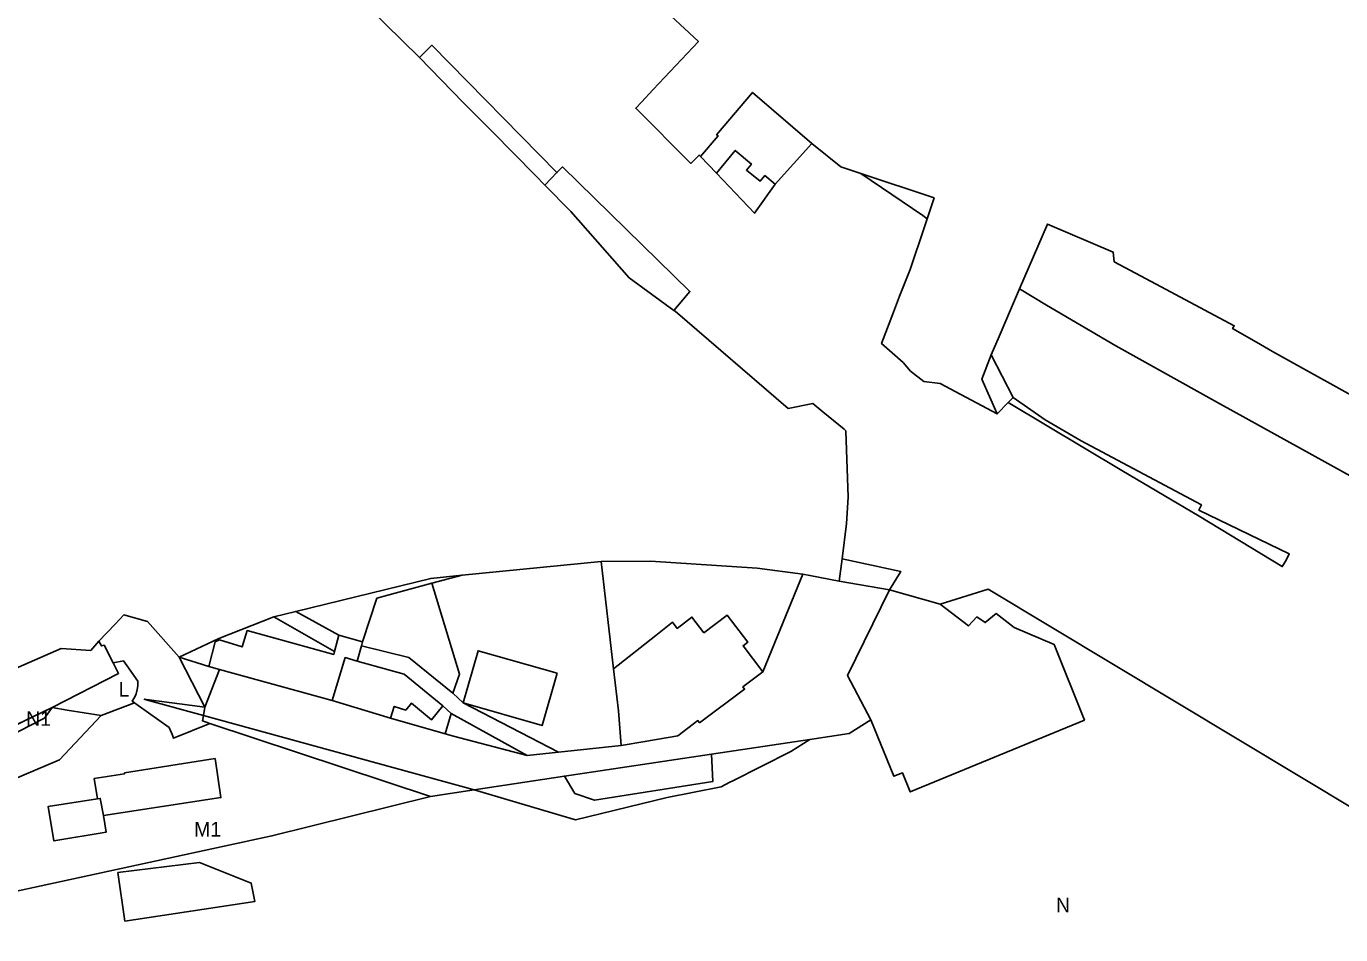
# Model space of a CAD drawing. Extents: x -749314 to -746497, y -1026537 to -1024935.
# Drawn here: x -748467.6 to -748241.9, y -1025301.1 to -1025145.2 of the extents above; entities that cross this region are included whole.
import ezdxf

# ---------------------------------------------------------------- set-up
doc = ezdxf.new("R2010")
doc.units = 0
for name, color, linetype in [('Default', 7, 'Continuous'), ('K_CD1', 7, 'Continuous'), ('K_DOSZDC1', 7, 'Continuous'), ('K_DOSZDC2', 7, 'Continuous'), ('K_JVL', 7, 'Continuous'), ('K_NH_SZDC', 7, 'Continuous'), ('K_SZDC1', 7, 'Continuous')]:
    doc.layers.add(name, color=color, linetype=linetype)

msp = doc.modelspace()

# ---------------------------------------------------------------- linework, layer by layer
at = {"layer": 'Default'}
msp.add_lwpolyline([(-748481.42, -1025296.24), (-748425.39, -1025284.16), (-748398.16, -1025277.36), (-748390.67, -1025276.23), (-748373.29, -1025281.41), (-748357.56, -1025277.57), (-748348.28, -1025275.71), (-748346.76, -1025274.95), (-748346.26, -1025274.69), (-748336.31, -1025269.68), (-748333.02, -1025267.6), (-748326.29, -1025266.59), (-748322.55, -1025264.22), (-748318.62, -1025273.91), (-748317.14, -1025273.32), (-748315.81, -1025276.61), (-748285.9, -1025264.26), (-748291.07, -1025251.31), (-748297.93, -1025248.38), (-748301.07, -1025245.99), (-748302.96, -1025247.53), (-748304.39, -1025246.58), (-748305.81, -1025248.11), (-748310.66, -1025244.41), (-748302.42, -1025241.8), (-748259.36, -1025267.68), (-748156.97, -1025329.23)], dxfattribs=at)
for points in [[(-748507.76, -1025270.01), (-748500.87, -1025267.55), (-748481.26, -1025260.55), (-748461.55, -1025251.98), (-748456.49, -1025252.31), (-748455.09, -1025250.76), (-748454.67, -1025251.54), (-748454.2, -1025251.4), (-748452.63, -1025254.43), (-748451.72, -1025256.27), (-748463.12, -1025262.12), (-748476.84, -1025268.7), (-748490.67, -1025269.69)], [(-748373.41, -1025276.86), (-748375.18, -1025273.89), (-748390.67, -1025276.23), (-748373.29, -1025281.41), (-748357.56, -1025277.57), (-748348.28, -1025275.71), (-748346.76, -1025274.95), (-748346.26, -1025274.69), (-748336.31, -1025269.68), (-748333.02, -1025267.6), (-748349.91, -1025270.15), (-748349.68, -1025274.79), (-748369.98, -1025278.03)], [(-748349.91, -1025270.15), (-748375.18, -1025273.89), (-748373.41, -1025276.86), (-748369.98, -1025278.03), (-748349.68, -1025274.79)], [(-748428.95, -1025292.23), (-748437.85, -1025288.69), (-748451.83, -1025290.44), (-748450.64, -1025298.75), (-748428.35, -1025295.41)], [(-748451.83, -1025290.44), (-748450.64, -1025298.75), (-748428.35, -1025295.41), (-748428.95, -1025292.23), (-748437.85, -1025288.69)]]:
    msp.add_lwpolyline(points, close=True, dxfattribs=at)
at = {"layer": 'K_CD1'}
for points in [[(-748397.91, -1025240.78), (-748392.75, -1025239.43), (-748368.84, -1025237.04), (-748366.72, -1025255.47), (-748365.9, -1025262.69), (-748365.42, -1025268.61), (-748376.21, -1025269.79), (-748392.57, -1025261.31), (-748394.34, -1025259.67), (-748393.18, -1025256.4)], [(-748413.88, -1025249.73), (-748409.82, -1025250.87), (-748407.37, -1025243.38), (-748397.91, -1025240.78), (-748392.75, -1025239.43), (-748398.11, -1025239.97), (-748421.29, -1025245.63)], [(-748409.82, -1025250.87), (-748410.01, -1025251.52), (-748401.89, -1025253.55), (-748394.34, -1025259.67), (-748393.18, -1025256.4), (-748397.91, -1025240.78), (-748407.37, -1025243.38)], [(-748343.7, -1025250.93), (-748347.24, -1025246.25), (-748351.22, -1025249.28), (-748353.27, -1025246.6), (-748355.8, -1025248.53), (-748356.59, -1025247.5), (-748359.49, -1025249.78), (-748366.72, -1025255.47), (-748365.9, -1025262.69), (-748365.42, -1025268.61), (-748361.35, -1025267.97), (-748355.72, -1025266.95), (-748352.26, -1025264.36), (-748351.98, -1025264.74), (-748344.24, -1025258.97), (-748344.54, -1025258.57), (-748341.12, -1025256), (-748344.5, -1025251.53)], [(-748376.44, -1025256.25), (-748389.99, -1025252.38), (-748392.57, -1025261.31), (-748379.01, -1025265.21)], [(-748452.63, -1025254.43), (-748450.89, -1025254.09), (-748450.31, -1025254.91), (-748448.41, -1025257.6), (-748448.41, -1025258.33), (-748448.5, -1025259.06), (-748448.7, -1025259.76), (-748448.98, -1025260.42), (-748449.36, -1025261.05), (-748448.96, -1025261.34), (-748454.73, -1025263.51), (-748460.54, -1025262.55), (-748463.12, -1025262.12), (-748451.72, -1025256.27)], [(-748402.41, -1025262.56), (-748404.38, -1025261.94), (-748405.01, -1025263.94), (-748395.64, -1025266.64), (-748394.62, -1025263.16), (-748396.07, -1025261.8), (-748398.01, -1025264.24), (-748401.44, -1025261.39)], [(-748476.84, -1025268.7), (-748473.31, -1025268.45), (-748473.2, -1025268.39), (-748464.42, -1025263.92), (-748463.12, -1025262.12), (-748460.54, -1025262.55), (-748454.73, -1025263.51), (-748461.87, -1025271.11), (-748472.17, -1025275.42), (-748531.33, -1025278.43), (-748493.03, -1025276.48)], [(-748463.12, -1025262.12), (-748464.42, -1025263.92), (-748473.2, -1025268.39), (-748473.31, -1025268.45), (-748490.67, -1025269.69), (-748476.84, -1025268.7)], [(-748436.05, -1025264.85), (-748398.16, -1025277.36), (-748390.67, -1025276.23), (-748437.15, -1025263.49), (-748437.32, -1025264.43)], [(-748395.64, -1025266.64), (-748394.19, -1025267.02), (-748381.58, -1025270.37), (-748394.62, -1025263.16)], [(-748455.36, -1025277.8), (-748463.83, -1025279.13), (-748462.81, -1025285), (-748453.87, -1025283.51), (-748454.31, -1025280.65), (-748434.14, -1025277.57), (-748435.16, -1025270.88), (-748450.7, -1025273.33), (-748450.68, -1025273.48), (-748455.91, -1025274.3)], [(-748434.14, -1025277.57), (-748435.16, -1025270.88), (-748450.7, -1025273.33), (-748450.68, -1025273.48), (-748455.91, -1025274.3), (-748455.36, -1025277.8), (-748454.86, -1025277.72), (-748454.31, -1025280.65)], [(-748454.86, -1025277.72), (-748455.36, -1025277.8), (-748463.83, -1025279.13), (-748462.81, -1025285), (-748453.87, -1025283.51), (-748454.31, -1025280.65)]]:
    msp.add_lwpolyline(points, close=True, dxfattribs=at)
msp.add_lwpolyline([(-748472.17, -1025275.42), (-748461.87, -1025271.11), (-748454.73, -1025263.51), (-748448.96, -1025261.34), (-748448.37, -1025261.75), (-748443.02, -1025265.56), (-748442.47, -1025266.89), (-748442.27, -1025267.38), (-748436.05, -1025264.85), (-748398.16, -1025277.36), (-748425.39, -1025284.16), (-748481.42, -1025296.24)], dxfattribs=at)
at = {"layer": 'K_DOSZDC1'}
for points in [[(-748361.64, -1025138.97), (-748352.17, -1025147.81), (-748359.92, -1025156.05), (-748361.94, -1025158.22), (-748362.94, -1025159.29), (-748353.45, -1025168.75), (-748352.05, -1025167.33), (-748351.8, -1025167.57), (-748349.06, -1025170.45), (-748342.56, -1025177.29), (-748338.97, -1025172.34), (-748332.71, -1025165.34), (-748327.72, -1025169.36), (-748324.28, -1025170.5), (-748313.64, -1025177.68), (-748312.91, -1025178.26), (-748313.36, -1025179.62), (-748315.81, -1025186.96), (-748317.62, -1025191.55), (-748318.68, -1025194.3), (-748320.73, -1025199.67), (-748318.92, -1025201.26), (-748317.03, -1025202.92), (-748315.73, -1025204.43), (-748313.48, -1025206.18), (-748310.68, -1025206.52), (-748300.87, -1025211.73), (-748298.96, -1025209.79), (-748279.45, -1025221.42), (-748266.2, -1025229.26), (-748251.92, -1025237.92), (-748251.29, -1025236.96), (-748250.72, -1025235.77), (-748266.23, -1025228.28), (-748265.8, -1025227.35), (-748286.48, -1025216.34), (-748292.62, -1025212.73), (-748298.12, -1025208.94), (-748301.88, -1025201.58), (-748300.52, -1025198.43), (-748298.39, -1025193.46), (-748297.03, -1025190.29), (-748292.38, -1025193.05), (-748280.52, -1025200.07), (-748262.56, -1025210.09), (-748239.75, -1025222.62)], [(-748156.97, -1025329.23), (-748259.36, -1025267.68), (-748302.42, -1025241.8), (-748310.66, -1025244.41), (-748319.38, -1025241.93), (-748317.42, -1025238.76), (-748327.51, -1025236.61), (-748326.73, -1025230.56), (-748326.47, -1025226.05), (-748326.87, -1025214.62), (-748327.16, -1025214.38), (-748330.78, -1025211.39), (-748332.52, -1025209.93), (-748336.74, -1025210.78), (-748356.18, -1025194.13), (-748356.37, -1025193.99), (-748355.74, -1025193.24), (-748353.64, -1025190.72), (-748375.48, -1025169.34), (-748376.46, -1025170.34), (-748397.91, -1025148.49), (-748400.03, -1025150.58), (-748408.87, -1025141.96)]]:
    msp.add_lwpolyline(points, dxfattribs=at)
at = {"layer": 'K_DOSZDC2'}
for points in [[(-748298.12, -1025208.94), (-748301.88, -1025201.58), (-748303.52, -1025205.77), (-748300.87, -1025211.73), (-748298.96, -1025209.79)], [(-748298.12, -1025208.94), (-748298.96, -1025209.79), (-748279.45, -1025221.42), (-748266.2, -1025229.26), (-748251.92, -1025237.92), (-748251.29, -1025236.96), (-748250.72, -1025235.77), (-748266.23, -1025228.28), (-748265.8, -1025227.35), (-748286.48, -1025216.34), (-748292.62, -1025212.73)], [(-748319.38, -1025241.93), (-748317.42, -1025238.76), (-748327.51, -1025236.61), (-748328, -1025240.41)]]:
    msp.add_lwpolyline(points, close=True, dxfattribs=at)
at = {"layer": 'K_JVL'}
for points in [[(-748378.54, -1025172.46), (-748376.46, -1025170.34), (-748397.91, -1025148.49), (-748400.03, -1025150.58), (-748392.55, -1025158.28), (-748389.34, -1025161.49), (-748387.51, -1025163.33), (-748380.2, -1025170.79)], [(-748356.37, -1025193.99), (-748355.74, -1025193.24), (-748353.64, -1025190.72), (-748375.48, -1025169.34), (-748376.46, -1025170.34), (-748378.54, -1025172.46), (-748374.05, -1025176.99), (-748364.05, -1025188.38)], [(-748324.28, -1025170.5), (-748313.64, -1025177.68), (-748312.91, -1025178.26), (-748311.72, -1025174.67)], [(-748231.61, -1025227.23), (-748231.28, -1025225.26), (-748226.09, -1025216.29), (-748236.47, -1025210.53), (-748253.59, -1025201.03), (-748256.36, -1025199.44), (-748260.46, -1025197.09), (-748260.18, -1025196.6), (-748275.28, -1025188.56), (-748280.8, -1025185.62), (-748280.97, -1025183.96), (-748292.24, -1025179.16), (-748297.03, -1025190.29), (-748292.38, -1025193.05), (-748280.52, -1025200.07), (-748262.56, -1025210.09), (-748239.75, -1025222.62)], [(-748342.1, -1025238.22), (-748360.41, -1025236.99), (-748368.84, -1025237.04), (-748366.72, -1025255.47), (-748359.49, -1025249.78), (-748356.59, -1025247.5), (-748355.8, -1025248.53), (-748353.27, -1025246.6), (-748351.22, -1025249.28), (-748347.24, -1025246.25), (-748343.7, -1025250.93), (-748344.5, -1025251.53), (-748341.12, -1025256), (-748334.22, -1025239.24)], [(-748375.18, -1025273.89), (-748349.91, -1025270.15), (-748333.02, -1025267.6), (-748326.29, -1025266.59), (-748322.55, -1025264.22), (-748326.56, -1025256.6), (-748319.38, -1025241.93), (-748328, -1025240.41), (-748333.03, -1025239.44), (-748334.22, -1025239.24), (-748341.12, -1025256), (-748344.54, -1025258.57), (-748344.24, -1025258.97), (-748351.98, -1025264.74), (-748352.26, -1025264.36), (-748355.72, -1025266.95), (-748361.35, -1025267.97), (-748365.42, -1025268.61), (-748376.21, -1025269.79), (-748381.58, -1025270.37), (-748394.19, -1025267.02), (-748395.64, -1025266.64), (-748405.01, -1025263.94), (-748415.04, -1025260.93), (-748434.4, -1025255.6), (-748436.89, -1025262.07), (-748437.15, -1025263.49), (-748390.67, -1025276.23)], [(-748414.64, -1025252.51), (-748413.88, -1025249.73), (-748421.29, -1025245.63), (-748425.08, -1025246.56)], [(-748446.77, -1025247.37), (-748450.79, -1025246.22), (-748452.32, -1025247.83), (-748455.09, -1025250.76), (-748454.67, -1025251.54), (-748454.2, -1025251.4), (-748452.63, -1025254.43), (-748450.89, -1025254.09), (-748450.31, -1025254.91), (-748448.41, -1025257.6), (-748448.41, -1025258.33), (-748448.5, -1025259.04), (-748448.7, -1025259.75), (-748448.98, -1025260.42), (-748449.36, -1025261.05), (-748448.96, -1025261.34), (-748448.37, -1025261.75), (-748443.02, -1025265.56), (-748442.47, -1025266.89), (-748442.27, -1025267.38), (-748436.05, -1025264.85), (-748437.32, -1025264.43), (-748437.15, -1025263.49), (-748446.99, -1025260.8), (-748447.3, -1025260.71), (-748446.93, -1025260.76), (-748436.89, -1025262.07), (-748441.31, -1025253.47)], [(-748412.81, -1025253.55), (-748410.75, -1025254.14), (-748410.01, -1025251.52), (-748409.82, -1025250.87), (-748413.88, -1025249.73), (-748414.64, -1025252.51), (-748414.77, -1025253), (-748429.63, -1025248.93), (-748430.48, -1025251.73), (-748434.39, -1025250.53), (-748435.12, -1025250.84), (-748436.23, -1025255.1), (-748434.4, -1025255.6), (-748415.04, -1025260.93)], [(-748402.71, -1025256.42), (-748396.07, -1025261.8), (-748394.62, -1025263.16), (-748381.58, -1025270.37), (-748376.21, -1025269.79), (-748392.57, -1025261.31), (-748394.34, -1025259.67), (-748401.89, -1025253.55), (-748410.01, -1025251.52), (-748410.75, -1025254.14)], [(-748434.4, -1025255.6), (-748436.23, -1025255.1), (-748441.31, -1025253.47), (-748436.89, -1025262.07)], [(-748415.04, -1025260.93), (-748405.01, -1025263.94), (-748404.38, -1025261.94), (-748402.41, -1025262.56), (-748401.44, -1025261.39), (-748398.01, -1025264.24), (-748396.07, -1025261.8), (-748402.71, -1025256.42), (-748410.75, -1025254.14), (-748412.81, -1025253.55)], [(-748446.93, -1025260.76), (-748447.3, -1025260.71), (-748446.99, -1025260.8), (-748437.15, -1025263.49), (-748436.89, -1025262.07)]]:
    msp.add_lwpolyline(points, close=True, dxfattribs=at)
at = {"layer": 'K_NH_SZDC'}
for points in [[(-748476.84, -1025268.7), (-748472.72, -1025266.73), (-748471.99, -1025266.38), (-748463.12, -1025262.12), (-748451.72, -1025256.27), (-748452.63, -1025254.43)], [(-748521.85, -1025290.46), (-748553.04, -1025306.14), (-748572.73, -1025313.98), (-748571.38, -1025316.98), (-748543.82, -1025309.98), (-748531.16, -1025305.07), (-748530.09, -1025307.69), (-748506.7, -1025300.58), (-748481.42, -1025296.24), (-748425.39, -1025284.16), (-748398.16, -1025277.36)]]:
    msp.add_lwpolyline(points, dxfattribs=at)
at = {"layer": 'K_SZDC1'}
for points in [[(-748349.06, -1025170.45), (-748345.83, -1025166.53), (-748343.06, -1025168.88), (-748343.94, -1025169.91), (-748341.54, -1025171.79), (-748340.74, -1025170.84), (-748338.97, -1025172.34), (-748332.71, -1025165.34), (-748342.88, -1025156.56), (-748349.05, -1025163.84), (-748348.77, -1025164.04), (-748351.8, -1025167.57)], [(-748342.56, -1025177.29), (-748338.97, -1025172.34), (-748340.74, -1025170.84), (-748341.54, -1025171.79), (-748343.94, -1025169.91), (-748343.06, -1025168.88), (-748345.83, -1025166.53), (-748349.06, -1025170.45)], [(-748305.81, -1025248.11), (-748310.66, -1025244.41), (-748319.38, -1025241.93), (-748326.56, -1025256.6), (-748322.55, -1025264.22), (-748318.62, -1025273.91), (-748317.14, -1025273.32), (-748315.81, -1025276.61), (-748285.9, -1025264.26), (-748291.07, -1025251.31), (-748297.93, -1025248.38), (-748301.07, -1025245.99), (-748302.96, -1025247.53), (-748304.39, -1025246.58)], [(-748414.64, -1025252.51), (-748425.08, -1025246.56), (-748434.48, -1025250.28), (-748441.31, -1025253.47), (-748436.23, -1025255.1), (-748435.12, -1025250.84), (-748434.39, -1025250.53), (-748430.48, -1025251.73), (-748429.63, -1025248.93), (-748414.77, -1025253)], [(-748376.44, -1025256.25), (-748389.99, -1025252.38), (-748392.57, -1025261.31), (-748379.01, -1025265.21)]]:
    msp.add_lwpolyline(points, close=True, dxfattribs=at)

# ---------------------------------------------------------------- texts
for s, p in [('L', (-748451.71, -1025260.25)), ('N1', (-748467.6, -1025265.25)), ('M1', (-748438.75, -1025284.25)), ('N', (-748290.78, -1025297.25))]:
    msp.add_text(s, height=2.5).set_placement(p)

doc.saveas('drawing.dxf')
